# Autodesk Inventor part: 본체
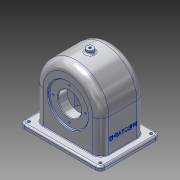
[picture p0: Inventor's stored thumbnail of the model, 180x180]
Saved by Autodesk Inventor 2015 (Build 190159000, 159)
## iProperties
Created: 2016-01
Part Number: 본체
Material: 알루미늄 6061
Document SubType Name: Modeling
Designer: 601-23
Density: 2.7 g/cm^3
Appearance: 알루미늄 - 평지
Mass: 756.185 g
Surface Area: 1009.81 cm^2
Volume: 280.069 cm^3
Author: 601-23
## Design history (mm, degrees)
sketch "스케치3"
  geometry: L1 (-57, 0)-(-57, -57); L2 (57, 0)-(57, -57); L3 (57, -57)-(-57, -57); A1 r 57 centre (0, 0) between (57, 0) and (-57, 0); 1 further point
  constraints: 6 end point, 2 point on circle, 2 tangent, 2 vertical, 1 centre point, 1 coincident, 1 perpendicular
  dimensions: "d5" = 114 diameter of A1; "d7" = 57 distance from line of L3 point (0, 0)
extrude "돌출2" new body sketch "스케치3" distance "d8" = 77; taper "d9" = 0 deg
node "작업 평면2"
sketch "스케치4"
  geometry: L1 (0, 0)-(0, 77) reference; L2 (0, 77)-(114, 77) reference; L3 (114, 77)-(114, 0) reference; L4 (114, 0)-(0, 0) reference; L5 (-13, 90.5)-(127, 90.5); L6 (127, 90.5)-(127, -13.5); L7 (127, -13.5)-(-13, -13.5); L8 (-13, -13.5)-(-13, 90.5); 5 further points
  constraints: 8 end point, 4 midpoint, 2 parallel, 1 horizontal, 1 horizontal alignment, 1 perpendicular, 1 vertical alignment
  dimensions: "d10" = 140 distance of L5.start L5.end; "d11" = 104 distance of L5.end L6.end
extrude "돌출3" join sketch "스케치4" distance "d12" = 7; taper "d13" = 0 deg
fillet "모깎기1" dims "d21" = 8
fillet "모깎기2" dims "d22" = 14
feature "쉘1" dims "d41" = 5
sketch "스케치11"
  geometry: L1 (0, 0)-(13.5, 0) reference; L2 (13.5, 0)-(13.5, -7) reference; L3 (13.5, -7)-(8.5, -7) reference; L4 (8.5, -7)-(8.5, -5) reference; L5 (8.5, -5)-(-5, -5) reference; L6 (-5, -5)-(-5, 100) reference; L7 (-14, 109)-(-63, 109) reference; L8 (-72, 100)-(-72, -5) reference; L9 (-72, -5)-(-85.5, -5) reference; L10 (-85.5, -5)-(-85.5, -7) reference; L11 (-85.5, -7)-(-90.5, -7) reference; L12 (-90.5, -7)-(-90.5, 0) reference; L13 (-90.5, 0)-(-77, 0) reference; L14 (-77, 0)-(-77, 100) reference; L15 (-63, 114)-(-14, 114) reference; L16 (0, 100)-(0, 0) reference; L17 (-77, 53)-(0, 53); L18 (-5, 57)-(-5, -5) reference; L19 (-72, -5)-(-72, 57) reference; L20 (-72, 57)-(-72, 100) reference; L21 (-72, 92.747)-(-58, 81); L22 (-58, 81)-(-58, 53); L23 (-72, 92.747)-(-72, 53); L24 (-77, 87.899)-(-74, 87.899); L25 (-74, 87.899)-(-74, 53); L26 (-74, 53)-(-77, 53); L27 (-77, 53)-(-77, 87.899); A1 r 9 centre (-14, 100) between (-5, 100) and (-14, 109) reference; A2 r 9 centre (-63, 100) between (-63, 109) and (-72, 100) reference; A3 r 14 centre (-63, 100) between (-63, 114) and (-77, 100) reference; A4 r 14 centre (-14, 100) between (0, 100) and (-14, 114) reference; 1 further point
  constraints: 16 end point, 8 point on line, 3 perpendicular, 2 parallel, 1 horizontal
  dimensions: "d42" = 60 distance between parallel lines of L3 L17; "d64" = 3 distance of L24.start L24.end; "d65" = 5 distance from line of L21 L24.end; "d66" = 50 deg angle of L22 L21; "d67" = 16 distance of L22.end L25.end; "d68" = 56 diameter of L21.end L17
  node "절단 모서리 투영7"
revolve "회전4" stored, may be unused: angle "d69" = 90 deg
sketch "스케치12"
  geometry: L1 (62, -64)-(-62, -64) reference; L2 (0, -4)-(0, 30.899) reference; L3 (0, -57)-(0, 43) reference; 3 further points
  constraints: 1 coincident, 1 vertical alignment, 2 other
extrude "돌출5" cut sketch "스케치12" distance "d71" = 3; taper "d72" = 0 deg
sketch "스케치13"
  geometry: C1 r 34.899 at (0, 0) reference; 2 further points
  constraints: 1 coincident
hole "구멍1" sketch "스케치13" at (0, 0) diameter "d73" = 40; stored, may be unused: countersink angle "d77" = 90 deg, drill point angle "d79" = 118 deg; dims "d74" = 6, "d75" = 4, "d76" = 2, "d78" = 8
sketch "스케치14"
  geometry: L1 (-43, -57)-(-43, 0) reference; L2 (-43, -57)-(43, -57) reference; L3 (43, 0)-(43, -57) reference; C1 r 20 at (0, -4) reference; C2 r 31 at (0, -4); A1 r 43 centre (0, 0) between (43, 0) and (-43, 0) reference; 1 further point
  constraints: 1 centre point, 1 coincident
  dimensions: "d80" = 62 diameter of C2
extrude "돌출6" join sketch "스케치14" distance "d81" = 10; taper "d82" = 0 deg
sketch "스케치15"
  geometry: L1 (124, 0)-(0, 0) reference; L2 (127, 91)-(127, 3) reference; L3 (0, 94)-(124, 94) reference; L4 (-3, 3)-(-3, 91) reference; L5 (105, 13.5)-(19, 13.5) reference; L6 (10, 22.5)-(10, 71.5) reference; L7 (19, 80.5)-(105, 80.5) reference; L8 (114, 22.5)-(114, 71.5) reference; A1 r 3 centre (0, 3) between (-3, 3) and (0, 0) reference; A2 r 3 centre (124, 3) between (124, 0) and (127, 3) reference; A3 r 3 centre (124, 91) between (127, 91) and (124, 94) reference; A4 r 3 centre (0, 91) between (0, 94) and (-3, 91) reference; A5 r 9 centre (19, 22.5) between (10, 22.5) and (19, 13.5) reference; A6 r 9 centre (19, 71.5) between (19, 80.5) and (10, 71.5) reference; A7 r 9 centre (105, 71.5) between (114, 71.5) and (105, 80.5) reference; A8 r 9 centre (105, 22.5) between (105, 13.5) and (114, 22.5) reference; 1 further point
extrude "돌출7" join sketch "스케치15" stored distance "d83" = 10; taper "d84" = 0 deg
fillet "모깎기3" dims "d85" = 1
fillet "모깎기4" dims "d86" = 3
sketch "스케치16"
  geometry: L1 (119, 10.5)-(-5, 10.5) reference; L2 (-10, 5.5)-(-10, -82.5) reference; L3 (-5, -87.5)-(119, -87.5) reference; L4 (124, -82.5)-(124, 5.5) reference; L5 (115, -63)-(115, -14) reference; L6 (14, 1)-(100, 1) reference; L7 (-1, -63)-(-1, -14) reference; L8 (100, -78)-(14, -78) reference; L9 (14, -72)-(100, -72) reference; L10 (109, -63)-(109, -14) reference; L11 (100, -5)-(14, -5) reference; L12 (5, -14)-(5, -63) reference; A1 r 5 centre (119, 5.5) between (124, 5.5) and (119, 10.5) reference; A2 r 5 centre (-5, 5.5) between (-5, 10.5) and (-10, 5.5) reference; A3 r 5 centre (-5, -82.5) between (-10, -82.5) and (-5, -87.5) reference; A4 r 5 centre (119, -82.5) between (119, -87.5) and (124, -82.5) reference; A5 r 15 centre (100, -63) between (100, -78) and (115, -63) reference; A6 r 15 centre (100, -14) between (115, -14) and (100, 1) reference; A7 r 15 centre (14, -14) between (14, 1) and (-1, -14) reference; A8 r 15 centre (14, -63) between (-1, -63) and (14, -78) reference; A9 r 9 centre (14, -63) between (5, -63) and (14, -72) reference; A10 r 9 centre (100, -63) between (100, -72) and (109, -63) reference; A11 r 9 centre (100, -14) between (109, -14) and (100, -5) reference; A12 r 9 centre (14, -14) between (14, -5) and (5, -14) reference; 5 further points
  constraints: 4 coincident
hole "구멍2" sketch "스케치16" at (-5, 5.5), (119, 5.5), (119, -82.5), (-5, -82.5) diameter "d87" = 5; stored, may be unused: countersink angle "d91" = 90 deg, drill point angle "d93" = 118 deg; dims "d88" = 6, "d89" = 4, "d90" = 2, "d92" = 8
fillet "모깎기5" dims "d94" = 1
chamfer "모따기1" distance "d95" = 1; stored, may be unused: second distance "d96" = 2, angle "d97" = 45 deg
fillet "모깎기6" dims "d98" = 3
sketch "스케치17" dims "d99" = 56
  geometry: L1 (-67, -53)-(-53.198, -53) reference; L2 (-51.66, -52)-(-51.66, 4) reference; L3 (51.66, 4)-(51.66, -52) reference; L4 (53.198, -53)-(67, -53) reference; L5 (70, -56)-(70, -60) reference; L6 (70, -60)-(-70, -60) reference; L7 (-70, -60)-(-70, -56) reference; C1 r 21 at (0, 0) reference; C2 r 33.899 at (0, 0) reference; A1 r 3 centre (-67, -56) between (-67, -53) and (-70, -56) reference; A2 r 51.66 centre (0, 4) between (51.66, 4) and (-51.66, 4) reference; A3 r 3 centre (67, -56) between (70, -56) and (67, -53) reference; 3 further points
  constraints: 2 vertical alignment, 1 coincident, 4 other
hole "구멍3" sketch "스케치17" at (0, 28) diameter "d100" = 3.242; stored, may be unused: countersink angle "d104" = 90 deg, drill point angle "d106" = 118 deg; dims "d101" = 7, "d102" = 4, "d103" = 2, "d105" = 9
sketch "스케치18" dims "d110" = 48
  geometry: L1 (68.614, -56)-(68.614, -60) reference; L2 (68.614, -60)-(-68.614, -60) reference; L3 (-68.614, -60)-(-68.614, -56) reference; L4 (-64.179, -53)-(64.179, -53) reference; C1 r 31 at (0, 0) reference; C2 r 21 at (0, 0) reference; 3 further points
  constraints: 2 vertical alignment, 1 coincident, 4 other
hole "구멍4" sketch "스케치18" at (0, 24) diameter "d111" = 3.242; stored, may be unused: countersink angle "d115" = 90 deg, drill point angle "d117" = 118 deg; dims "d112" = 6, "d113" = 4, "d114" = 2, "d116" = 8
node "작업 평면4"
  node "작업 평면3"
sketch "스케치19"
  geometry: L1 (57, 63)-(-57, 63) reference; L2 (57, 14)-(57, 63) reference; L3 (-57, 14)-(57, 14) reference; L4 (-57, 14)-(-57, 63) reference; C1 r 6 at (0, 38.5); 2 further points
  constraints: 1 centre point, 1 horizontal alignment, 1 midpoint, 1 vertical alignment
  dimensions: "d122" = 12 diameter of C1
extrude "돌출8" join sketch "스케치19" stored distance "d123" = 10; taper "d124" = 0 deg
hole "구멍5" diameter "d127" = 4.134; stored, may be unused: countersink angle "d131" = 90 deg, drill point angle "d133" = 118 deg; dims "d125" = 10, "d126" = 10, "d128" = 10, "d129" = 4, "d130" = 2, "d132" = 33.95
sketch "스케치20"
  geometry: L1 (76.5, -60)-(76.5, -64) reference; L2 (76.5, -64)-(-27.5, -64) reference; L3 (-27.5, -64)-(-27.5, -60) reference; L4 (-24.5, -57)-(-5.385, -57) reference; L5 (0, -56)-(49, -56) reference; L6 (54.385, -57)-(73.5, -57) reference; L7 (0, -56)-(0, 0) reference; L8 (49, 0)-(0, 0) reference; L9 (49, 0)-(49, -56) reference; L10 (68.5, -64)-(-19.5, -64) reference; A1 r 3 centre (73.5, -60) between (76.5, -60) and (73.5, -57) reference; A2 r 3 centre (-24.5, -60) between (-24.5, -57) and (-27.5, -60) reference; 3 further points
  constraints: 1 midpoint, 1 vertical alignment, 3 other
  dimensions: "d134" = 30 distance from line of L2 point (24.5, -34)
feature "엠보싱1" sketch "스케치20" dims "d135" = 0.5, "d136" = 0
fillet "모깎기7" dims "d137" = 3
chamfer "모따기2" distance "d138" = 1; stored, may be unused: second distance "d139" = 2, angle "d140" = 45 deg
node "솔리드2"
pattern_circular "원형 패턴1" dims angle "d108" = 360 deg
pattern_circular "원형 패턴2" dims angle "d119" = 360 deg
node "투영된 루프1"
node "투영된 루프2"
node "투영된 루프3"
node "투영된 루프4"
node "절단 모서리 투영2"
node "절단 모서리 투영8"
node "절단 모서리 투영9"
node "절단 모서리 투영10"
node "절단 모서리 투영11"
other parameters: "d121" = -6
